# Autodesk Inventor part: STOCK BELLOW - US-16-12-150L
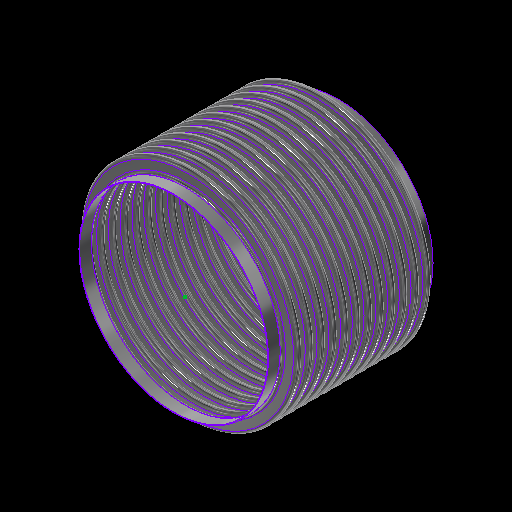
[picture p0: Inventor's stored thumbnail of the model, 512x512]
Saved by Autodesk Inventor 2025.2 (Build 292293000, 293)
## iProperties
Category: 16 GA (0.060 THICK)
RuleStatus: InUse
Created: 2024-01
Part Number: STOCK BELLOW - US-16-12-150L
Project: =STOCK BELLOWS: <Stock Number><SFILL>
Material: ASTM A240-304
Description: =STOCK BELLOWS: <Stock Number>, <SID_> I.D., <SOD_> O.D., <SPLY_> PLY, <Category>, <SNET_CONS> CONS.<PITCH_><STANGENT_> TANGENT<SFILL>
Document SubType Name: Sheet Metal
Designer: GS
Stock Number: U.S-16-12-150L
Surface Area: 26179.6 cm^2
Volume: 1985.95 cm^3
Sheet Metal Rule: Default
Appearance: STAINLESS STEEL
Mass: 16001.4 g
Density: 8.05729 g/cm^3
THK: 0.036
ID: 3.500
OD: 4.250
CONS_: 2
PITCH: 0.500
TANGENT: 0.500
BELLOWS_UPSET: 0.000
d79: 1.000
d82: 1.000
d83: 26.000
d84: 24.000
d174: 8
d214: 8
STHK_: 0.060
SID_: 16.000
SOD_: 18.500
SPITCH_: 1.000
STANGENT__: 1.000
SBELLOWS_UPSET_: 0.000
SDIFF_TAN: 1.000
d252: 2
d275: 2
d287: 0.050
d289: 0.500
d290: 0.000
SOD_NECK: 16 1/8
PLY: 1
PSET: 4.178
PBAR: 1.035
COUNTER: 1.500
NET_TUBE: 3.071
CONS: 2
S_CONS: 0
NET_CONS: 2
ID_M: 88.90 mm
OD_M: 107.95 mm
THK_M: 0.91 mm
ID_U: 3.500 in
OD_U: 4.250 in
THK_U: 0.036 in
TANGENT2: 0.500
TAN_TO_TAN: 1.000 in
d80: 2.571
d81: 10
SID: 2.375
SCONS_: 12
SPITCH: 0.250
STANGENT_: 1.000
SBELLOWS_UPSET: 0.000
SNET_CONS: 12
SS_CONS: 0
SCONS: 8
d190: 8
d191: 1
d192: 1
d193: 8
d194: 0
SIZE: 16.00
PRESSURE: 150
d230: 8
STANGENT: 4.000
SPLY_: 1
d233: 8
d234: 0
d263: 2
d265: 1
d268: 2
d269: 0
d286: 2
d288: 1
d291: 2
d292: 0
SREROLL: 0.750
BLETP: 1.000 ul
PRES_Copy: 85
MATTABLE: 20 GA (0.036 THICK)
PART_NUMBER: U.S-16-12-150L
PITCH_: =, <SPITCH_> PITCH,
CFILL: .
SFILL: .
MESH: ,
COMP: 2.28
EXT: 1.14
LAT: 0.52
ANG: 573
ASR: 2982
LSR: 8318
ANSR: 1742
PRES: 150
COMPM: 22.8
EXTM: 11.4
LATM: 5.20
ASRM: 522.238
PRESM: 10.342
LSRM: 1456.731
ANSRM: 305.076
TEMPMIN: 20
TEMPMAX: 800
TEMPMINM: -7
TEMPMAXM: 427
WEIGHTM: 16.001
WEIGHT: 35.277
Author: GS
Keywords: 20 GA (0.036 THICK)
Comments: =STOCK BELLOW - <STOCK NUMBER>
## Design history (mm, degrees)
sketch "Sketch2"
  geometry: L1 (0, -177.245)-(0, 562.856) reference; L2 (45.364, 0)-(44.45, 0); L3 (48.082, -2.718)-(50.343, -2.718); L4 (48.082, -3.632)-(50.343, -3.632); L5 (50.343, -9.982)-(48.082, -9.982); L6 (50.343, -9.068)-(48.082, -9.068); L7 (45.364, -12.7)-(44.45, -12.7); L8 (48.082, 0)-(48.082, -12.7); L9 (50.343, -6.35)-(53.975, -6.35); L10 (44.45, 0)-(44.45, -12.7); L11 (20.376, 102.841)-(20.376, 101.926); L12 (58.262, 457.127)-(58.262, 349.177); L13 (58.262, 444.427)-(58.262, 336.477); L14 (93.133, -58.817)-(93.133, -71.517); L15 (118.746, -66.401)-(118.746, -66.401); L16 (50.343, -9.068)-(50.343, -9.982); L17 (48.082, -9.068)-(48.082, -9.982); L18 (48.082, -9.525)-(50.343, -9.525); L19 (53.975, 0)-(53.975, -12.7); L20 (-50.343, -9.068)-(-50.343, -9.982); L21 (-50.343, -2.718)-(-48.082, -2.718); L22 (-50.343, -3.632)-(-48.082, -3.632); L23 (-48.082, -9.068)-(-50.343, -9.068); L24 (-50.343, -9.525)-(-48.082, -9.525); L25 (-48.082, -9.982)-(-50.343, -9.982); L26 (-48.082, -9.068)-(-48.082, -9.982); L27 (-44.45, 0.653)-(-44.45, -12.047); L28 (-48.082, -6.35)-(-44.45, -6.35); L29 (-50.343, 0.653)-(-50.343, -12.7); L30 (-53.061, 0)-(-53.975, 0); L31 (-53.975, 0)-(-53.975, -12.7); L32 (-53.061, -12.7)-(-53.975, -12.7); A1 r 2.718 centre (48.082, 0) between (45.364, 0) and (48.082, -2.718); A2 r 3.632 centre (48.082, 0) between (44.45, 0) and (48.082, -3.632); A3 r 3.632 centre (50.343, -6.35) between (50.343, -9.982) and (50.343, -2.718); A4 r 2.718 centre (50.343, -6.35) between (50.343, -9.068) and (50.343, -3.632); A5 r 2.718 centre (48.082, -12.7) between (48.082, -9.982) and (45.364, -12.7); A6 r 3.632 centre (48.082, -12.7) between (48.082, -9.068) and (44.45, -12.7); A7 r 3.175 centre (50.343, -6.35) between (50.343, -9.525) and (53.518, -6.35); A8 r 3.175 centre (48.082, -12.7) between (48.082, -9.525) and (44.907, -12.7); A9 r 2.718 centre (-50.343, -12.7) between (-50.343, -9.982) and (-53.061, -12.7); A10 r 2.718 centre (-48.082, -6.35) between (-48.082, -9.068) and (-48.082, -3.632); A11 r 3.175 centre (-48.082, -6.35) between (-48.082, -9.525) and (-44.907, -6.35); A12 r 3.632 centre (-48.082, -6.35) between (-48.082, -9.982) and (-48.082, -2.718); A13 r 3.175 centre (-50.343, -12.7) between (-50.343, -9.525) and (-53.518, -12.7); A14 r 3.632 centre (-50.343, -12.7) between (-50.343, -9.068) and (-53.975, -12.7); A15 r 2.718 centre (-50.343, 0) between (-53.061, 0) and (-50.343, -2.718); A16 r 3.632 centre (-50.343, 0) between (-53.975, 0) and (-50.343, -3.632); 10 further points
  constraints: 62 end point, 38 point on circle, 20 tangent, 16 centre point, 12 parallel, 9 midpoint, 7 vertical, 6 coincident, 6 concentric, 6 point on line, 4 equal radius, 4 perpendicular, 3 horizontal, 1 collinear, 1 horizontal alignment, 10 other
  dimensions: "THK" = 0.9144 distance of L11.start L11.end; "ID" = 88.9 distance of L11.end point (20.376, 13.026); "OD" = 107.95 distance of L12.start L12.end; "PITCH" = 12.7 distance of L12.start L13.start; "TANGENT" = 12.7 distance of L14.start L14.end; "BELLOWS_UPSET" = 0 distance of L15.start L15.end; "d43" = 88.9 diameter of L10 L1 (= ID); "d44" = 107.95 diameter of L9.end L1 (= OD); "d45" = 0.9144 distance between parallel lines of L5 L6 (computed from THK, PLY); "d46" = 3.6322 radius of A3 (computed from PITCH, THK, PLY); "UPSET_PITCH" = 12.7 distance of L2.end L7.end (derived); "SIDEWALL_ANGLE" = 360 deg dimension on L3 L9 (derived); "CON_GAP" = 5.4356 distance of point (48.082, -9.068) point (48.082, -3.632) (derived); "TAN1" = 4.98728 dimension on A8 (derived); "TAN2" = 4.98728 dimension on A7 (derived); "LEG1" = 2.2606 distance of L18.start L18.end (derived); "d278" = 0.9144 distance between parallel lines of L25 L23 (derived); "d279" = 3.6322 radius of A12 (derived); "d280" = 12.7 distance of L30.end L31.end (derived); "d281" = 360 deg dimension on L21 L28 (derived); "d282" = 5.4356 distance of point (-50.343, -9.068) point (-50.343, -3.632) (derived); "d283" = 4.98728 dimension on A13 (derived); "d284" = 4.98728 dimension on A11 (derived); "d285" = 2.2606 distance of L24.start L24.end (derived); "d293" = 88.9 diameter of L27 L1 (derived); "d294" = 107.95 diameter of L31 L1 (derived)
  node "Sketch Rectangular Pattern1" dims "d31" = 25.4, "ID" = 88.9
  node "Sketch Rectangular Pattern2" dims "d39" = 25.4, "PITCH" = 12.7
revolve "CONS" stored, may be unused: angle "d48" = 90 deg
node "BELLOW MIDPLANE"
pattern_linear "Rectangular Pattern2" dims "d52" = 12.7 (= UPSET_PITCH)
sketch "Sketch5"
  geometry: C1 r 45.364 at (0, 0) reference; C2 r 44.45 at (0, 0) reference
extrude "TANGENT" new body sketch "Sketch5" distance "d53" = 12.7 (= TANGENT); taper "d54" = 0 deg
revolve "SAMETAN" stored, may be unused: angle "d65" = 90 deg
revolve "DIFFTAN" stored, may be unused: angle "d70" = 90 deg
sketch "Sketch9"
  geometry: L1 (53.319, 0)-(-53.319, 0) reference; L2 (0, -17.78)-(0, 17.78) reference; L3 (38.085, 0)-(-38.085, 0); L4 (38.085, -11.906)-(38.085, 11.906); L5 (25.385, -11.906)-(25.385, 11.906); L6 (13.15, 11.906)-(13.15, -11.906); L7 (-25.385, -11.906)-(-25.385, 11.906); L8 (-38.085, -11.906)-(-38.085, 11.906); L9 (37.291, -11.906)-(37.291, 11.906); L10 (38.085, -11.906)-(37.291, -11.906); L11 (38.085, 11.906)-(37.291, 11.906); L12 (13.546, 11.906)-(12.753, 11.906); L13 (12.753, 11.906)-(12.753, -11.906); L14 (12.753, -11.906)-(13.546, -11.906); L15 (13.546, -11.906)-(13.546, 11.906); L16 (-13.546, 11.906)-(-13.546, -11.906); L17 (-13.15, 11.906)-(-13.15, -11.906); L18 (-13.546, -11.906)-(-12.753, -11.906); L19 (-12.753, -11.906)-(-12.753, 11.906); L20 (-12.753, 11.906)-(-13.546, 11.906); L21 (-38.085, -11.906)-(-37.291, -11.906); L22 (-37.291, -11.906)-(-37.291, 11.906); L23 (-37.291, 11.906)-(-38.085, 11.906); L24 (-38.085, 11.906)-(-38.085, -11.906); L25 (38.085, -0.397)-(-38.085, -0.397); L26 (-38.085, -0.397)-(-38.085, 0.397); L27 (-38.085, 0.397)-(38.085, 0.397); L28 (38.085, 0.397)-(38.085, -0.397); L29 (-38.085, 11.906)-(38.085, 11.906); L30 (38.085, 11.906)-(38.085, 12.7); L31 (38.085, 12.7)-(-38.085, 12.7); L32 (-38.085, 12.7)-(-38.085, 11.906); L33 (38.085, -11.906)-(-38.085, -11.906); L34 (-38.085, -11.906)-(-38.085, -12.7); L35 (-38.085, -12.7)-(38.085, -12.7); L36 (38.085, -12.7)-(38.085, -11.906); 30 further points
  constraints: 68 end point, 13 midpoint, 13 parallel, 8 horizontal, 7 perpendicular, 6 equal length, 3 point on line, 2 vertical, 14 other
  dimensions: "d115" = 23.8125 distance of L4.start L4.end (derived); "d116" = 12.7 distance between parallel lines of L4 L5 (derived); "d117" = 12.23516 distance between parallel lines of L5 L6 (derived); "d125" = 38.53427 distance between parallel lines of L7 L6 (derived); "d127" = 12.7 distance between parallel lines of L8 L7 (derived); "d128" = 24.93516 distance between parallel lines of L6 L4 (derived); "d130" = 76.16943 distance between parallel lines of L8 L4 (derived); "RULER_THK" = 0.79375 distance between parallel lines of L4 L9; "d135" = 0.79375 distance of L13.end L14.end (derived); "d138" = 26.29911 distance of L13.end L16.end (derived); "d143" = 0.79375 distance of L22.end L8.end (derived); "d144" = 0.79375 distance between parallel lines of L27 L25 (derived)
extrude "RULER" join sketch "Sketch9" distance "d149" = 0.79375 (derived); taper "d150" = 0 deg
extrude "BARS" join sketch "Sketch9" distance "d151" = 0.79375 (derived); taper "d152" = 0 deg
pattern_linear "Rectangular Pattern4" dims "d155" = 26.29911 (derived)
sketch "Sketch13"
  geometry: L1 (93.149, -52.467)-(93.149, -77.867); L2 (204.724, 0)-(203.2, 0); L3 (204.724, -25.4)-(203.2, -25.4); L4 (227.838, -19.812)-(210.312, -19.812); L5 (227.838, -18.288)-(210.312, -18.288); L6 (227.838, -12.7)-(234.95, -12.7); L7 (210.312, -5.588)-(227.838, -5.588); L8 (210.312, 0)-(210.312, -25.4); L9 (203.2, 0)-(203.2, -25.4); L10 (58.254, -26.531)-(58.254, -496.431); L11 (58.254, -51.931)-(58.254, -521.831); L12 (58.254, -102.731)-(58.254, -572.631); L13 (58.254, -128.131)-(58.254, -598.031); L14 (58.254, -153.531)-(58.254, -623.431); L15 (58.254, -178.931)-(58.254, -648.831); L16 (58.254, -204.331)-(58.254, -674.231); L17 (58.254, -77.331)-(58.254, -547.231); L18 (20.376, 103.45)-(20.376, 101.926); L19 (210.312, -7.112)-(227.838, -7.112); L20 (0, -829.767)-(0, 258.986) reference; L21 (-46.99, 0)-(281.94, 0) reference; A1 r 5.588 centre (210.312, 0) between (204.724, 0) and (210.312, -5.588); A2 r 5.588 centre (210.312, -25.4) between (210.312, -19.812) and (204.724, -25.4); A3 r 7.112 centre (210.312, -25.4) between (210.312, -18.288) and (203.2, -25.4); A4 r 5.588 centre (227.838, -12.7) between (227.838, -18.288) and (227.838, -7.112); A5 r 7.112 centre (227.838, -12.7) between (227.838, -19.812) and (227.838, -5.588); A6 r 7.112 centre (210.312, 0) between (203.2, 0) and (210.312, -7.112); 6 further points; 1 other entity
  constraints: 38 end point, 15 point on circle, 9 tangent, 6 centre point, 6 parallel, 5 vertical alignment, 4 point on line, 4 vertical, 3 coincident, 3 concentric, 2 collinear, 2 equal radius, 1 horizontal, 1 perpendicular, 23 other
  dimensions: "SBELLOWS_UPSET_" = 0 distance of point (118.762, -66.401) point (118.762, -66.401); "STOTAL_THK_BELLOW__" = 1.524 distance between parallel lines of L4 L5 (derived); "d224" = 7.112 radius of A5 (derived); "d225" = 25.4 distance of L2.end L3.end (derived); "SSIDEWALL_ANGLE_" = 360 deg dimension on L7 L6 (derived); "SSCON_GAP_" = 11.176 distance of point (210.312, -18.288) point (210.312, -7.112) (derived); "d235" = 406.4 diameter of L9 L20 (derived); "d236" = 469.9 diameter of L6.end L20 (derived)
  node "Sketch Rectangular Pattern4" dims "d228" = 25.4
  node "Sketch Rectangular Pattern5" dims "d229" = 25.4
revolve "SBELLOW" stored, may be unused: angle "d197" = 90 deg
pattern_linear "Rectangular Pattern5" dims "d204" = 25.4 (derived)
revolve "STANGENT" stored, may be unused: angle "d240" = 90 deg
revolve "SSAMETAN" stored, may be unused: angle "d241" = 90 deg
revolve "SDIFFTAN" stored, may be unused: angle "d246" = 90 deg
revolve "INVCON" stored, may be unused: angle "d295" = 90 deg
pattern_linear "Rectangular Pattern6" dims "d298" = 12.7 (derived)
revolve "INVTANGENT" stored, may be unused: angle "d302" = 90 deg
revolve "INVSAMETAN" stored, may be unused: angle "d307" = 90 deg
revolve "INVDIFFTAN" stored, may be unused: angle "d312" = 90 deg
sketch "ID BELLOW MOUNT CALC"
  geometry: L1 (44.45, 0)-(38.1, 0); L2 (38.1, 0)-(38.1, 12.7); L3 (38.1, 12.7)-(44.45, 12.7); L4 (44.45, 12.7)-(44.45, 0); L5 (36.513, 12.7)-(35.598, 12.7); L6 (35.598, 12.7)-(35.598, 0); L7 (35.598, 0)-(36.513, 0); L8 (36.513, 0)-(36.513, 12.7); L9 (0, -2.54)-(0, 15.24) reference; L10 (-8.89, 0)-(53.34, 0) reference; 1 further point
  constraints: 16 end point, 5 parallel, 2 collinear, 2 horizontal, 2 perpendicular
  dimensions: "d314" = 12.7 distance of L5.end L6.end (derived); "d315" = 0.9144 distance of L5.start L5.end (derived); "IG" = 1.5875 distance between parallel lines of L2 L8; "PIPE_OD" = 88.9 diameter of L4 L9; "PIPE_WALL" = 6.35 distance of L2.end L3.end; "ID_MT_BELLOW" = 71.1962 diameter of L6 L9 (derived)
revolve "CFILL" stored, may be unused: angle "d320" = 90 deg
pattern_linear "Rectangular Pattern7" dims "d323" = 12.7 (derived)
revolve "SFILL" stored, may be unused: angle "d324" = 90 deg
pattern_linear "Rectangular Pattern8" dims "d327" = 25.4 (derived)
node "STOCK BELLOW MIDPLANE"
node "BELLOW"
sketch "Sketch6"
  geometry: L1 (-12.7, 45.364)-(0, 45.364); L2 (0, 45.364)-(0, 44.45); L3 (0, 44.45)-(-12.7, 44.45); L4 (-12.7, 44.45)-(-12.7, 45.364); L5 (10.16, 0)-(-60.96, 0) reference; L6 (-38.1, -89.422)-(-38.1, 153.44) reference; 1 further point
  constraints: 8 end point, 2 parallel, 1 horizontal, 1 perpendicular
  dimensions: "d61" = 12.7 distance of L2.end L3.end (derived); "d62" = 0.9144 distance of L1.end L2.end (derived); "d63" = 88.9 diameter of L3 L5 (derived); "d64" = 25.4 distance between parallel lines of L4 L6 (derived)
sketch "Sketch12"
  geometry: 1 further point
sketch "Sketch14"
  geometry: L1 (-25.4, 204.724)-(0, 204.724); L2 (0, 204.724)-(0, 203.2); L3 (0, 203.2)-(-25.4, 203.2); L4 (-25.4, 203.2)-(-25.4, 204.724); L5 (5.08, 0)-(-30.48, 0) reference; L6 (0, -40.945)-(0, 245.669) reference; 1 further point
  constraints: 8 end point, 2 parallel, 1 collinear, 1 horizontal, 1 perpendicular
  dimensions: "d237" = 1.524 distance of L3.end L1.start (derived); "d238" = 406.4 diameter of L3 L5 (derived); "d239" = 25.4 distance of L1.start L1.end (derived); "SOD_NECK" = 409.448 diameter of L1 L5 (derived)
sketch "Sketch15"
  geometry: L1 (-40.945, 0)-(245.669, 0) reference; L2 (203.2, -304.8)-(204.724, -304.8); L3 (204.724, -304.8)-(204.724, -330.2); L4 (204.724, -330.2)-(203.2, -330.2); L5 (203.2, -330.2)-(203.2, -304.8); L6 (0, -398.78)-(0, 81.28) reference; 1 further point
  constraints: 8 end point, 2 parallel, 1 horizontal, 1 perpendicular
  dimensions: "d205" = 25.4 distance of L4.end L2.start (derived); "d206" = 1.524 distance of L3.end L4.end (derived); "d207" = 406.4 diameter of L5 L6 (derived); "d208" = 304.8 distance between parallel lines of L1 L2 (derived)
node "TANGENT_"
node "SAME_TAN"
sketch "Sketch8"
  geometry: L1 (45.364, -25.4)-(44.45, -25.4); L2 (44.45, -25.4)-(44.45, -38.1); L3 (44.45, -38.1)-(45.364, -38.1); L4 (45.364, -38.1)-(45.364, -25.4); L5 (0, -48.26)-(0, 22.86) reference; L6 (-89.422, 0)-(153.44, 0) reference; 1 further point
  constraints: 8 end point, 2 parallel, 1 horizontal, 1 perpendicular
  dimensions: "d66" = 88.9 diameter of L2 L5 (derived); "TOTAL_THK_BELLOW" = 0.9144 distance of L2.end L3.end (derived); "d68" = 25.4 distance between parallel lines of L1 L6 (derived); "d69" = 12.7 distance of L1.end L2.end (derived)
node "DIFF_TAN"
node "Sketch Rectangular Pattern3" dims "d138" = 26.29911 (derived), "d141" = 25.4
node "SBELLOW_"
node "STANGENT_"
node "SSAME_TAN"
sketch "Sketch16"
  geometry: L1 (204.724, -304.8)-(203.2, -304.8); L2 (203.2, -304.8)-(203.2, -330.2); L3 (203.2, -330.2)-(204.724, -330.2); L4 (204.724, -330.2)-(204.724, -304.8); L5 (0, -398.78)-(0, 81.28) reference; L6 (-40.945, 0)-(245.669, 0) reference; 1 further point
  constraints: 8 end point, 2 parallel, 1 horizontal, 1 perpendicular
  dimensions: "SDIFF_TAN" = 25.4 distance of L3.end L1.start; "d243" = 1.524 distance of L2.end L3.end (derived); "d244" = 304.8 distance between parallel lines of L1 L6 (derived); "d245" = 406.4 diameter of L2 L5 (derived)
node "SDIFF_TAN"
body "Solid15"
sketch "Sketch17"
  geometry: L1 (53.975, 12.7)-(53.061, 12.7); L2 (53.061, 12.7)-(53.061, 0); L3 (53.061, 0)-(53.975, 0); L4 (53.975, 0)-(53.975, 12.7); L5 (0, -2.54)-(0, 15.24) reference; L6 (-10.795, 0)-(64.77, 0) reference; 2 further points
  constraints: 8 end point, 2 parallel, 1 horizontal, 1 midpoint, 1 perpendicular, 1 point on line
  dimensions: "INVTANGENT" = 12.7 distance of L3.end L1.start (derived); "d300" = 0.9144 distance of L1.start L1.end (derived); "d301" = 107.95 diameter of L4 L5 (derived)
body "Solid16"
sketch "Sketch18"
  geometry: L1 (53.975, -25.4)-(53.061, -25.4); L2 (53.061, -25.4)-(53.061, -38.1); L3 (53.061, -38.1)-(53.975, -38.1); L4 (53.975, -38.1)-(53.975, -25.4); L5 (-10.795, 0)-(64.77, 0) reference; L6 (0, -48.26)-(0, 22.86) reference; 1 further point
  constraints: 8 end point, 2 parallel, 1 horizontal, 1 perpendicular
  dimensions: "d303" = 25.4 distance between parallel lines of L1 L5 (derived); "d304" = 12.7 distance of L3.end L1.start (derived); "d305" = 0.9144 distance of L2.end L3.end (derived); "d306" = 107.95 diameter of L4 L6 (derived)
body "Solid17"
sketch "Sketch19"
  geometry: L1 (53.975, -25.4)-(53.061, -25.4); L2 (53.061, -25.4)-(53.061, -38.1); L3 (53.061, -38.1)-(53.975, -38.1); L4 (53.975, -38.1)-(53.975, -25.4); L5 (0, -48.26)-(0, 22.86) reference; L6 (-10.795, 0)-(64.77, 0) reference; 1 further point
  constraints: 8 end point, 2 parallel, 1 horizontal, 1 perpendicular
  dimensions: "d308" = 12.7 distance of L1.end L2.end (derived); "d309" = 107.95 diameter of L4 L5 (derived); "d310" = 0.9144 distance of L2.end L3.end (derived); "d311" = 25.4 distance between parallel lines of L1 L6 (derived)
body "Solid18"
body "Solid19"
body "Solid20"
other parameters: "BMPL" = -152.4, "PSET" = 106.1212 (computed from OD, THK, PLY) [user parameter], "PBAR" = 26.29911 (= 0.570796 x PITCH + OD - ID) [user parameter; used in 1 equation term], "COUNTER" = 15 [user parameter], "NET_TUBE" = 77.99823 (computed from CONS_, PBAR, TANGENT) [user parameter], "S_CONS" = 0 [user parameter; used in 1 equation term], "ID_M" = 88.9 (= ID) [user parameter], "OD_M" = 107.95 (= OD) [user parameter], "THK_M" = 0.9144 (= THK) [user parameter], "ID_U" = 88.9 (= ID) [user parameter], "OD_U" = 107.95 (= OD) [user parameter], "THK_U" = 0.9144 (= THK) [user parameter], "D_UNITS" = 0 [user parameter], "TANGENT2" = 12.7 [user parameter], "TAN_TO_TAN" = 25.4 [user parameter], "OD_NECK" = 90.7288 [user parameter], "d79" = 25.4, "d80" = 65.29823 [user parameter], "d82" = 25.4, "d83" = 660.4, "d84" = 609.6, "sa_0" = 4, "FRAME_THK" = 0.79375 [user parameter], "CON_FLAT" = 12.23516 [user parameter], "SID" = 60.325 [user parameter], "SPITCH" = 6.35 [user parameter], "STANGENT_" = 25.4 [user parameter], "SBELLOWS_UPSET" = 0 [user parameter], "SS_CONS" = 0 [user parameter], "STAN_TO_TAN_" = 304.8 [user parameter], "d100" = 1.524 [user parameter], "d191" = 25.4 [user parameter], "d194" = 0 [user parameter], "STANGENT" = 101.6 [user parameter], "d234" = 0 [user parameter], "SUPSET_PITCH_" = 25.4 [user parameter], "d269" = 0 [user parameter], "d287" = 1.27, "d289" = 12.7, "d290" = 0, "d292" = 0 [user parameter], "Thickness" = 3.048 (derived), "KFactor" = 4.4, "BendRadius" = 3.048 (derived), "BendReliefWidth" = 3.048 (derived), "BendReliefDepth" = 1.524 (derived), "CornerReliefSize" = 12.192 (derived), "SeamGap" = 0.00508, "MinimumRemnant" = 6.096 (derived), "TransitionRadius" = 3.048 (derived), "JacobiRadiusSize" = 3.048 (derived), "GapSize" = 3.048 (derived), "SREROLL" = 19.05 [user parameter], "CUR_STK_PITCH" = 25.4 [user parameter], "d328" = -152.4 (derived), "ASR" = 29820 [user parameter], "LSR" = 83180 [user parameter], "ANSR" = 17420 [user parameter], "BLETP" = 1 [user parameter], "ASRM" = 5222.3766 [user parameter], "PRESM" = 103.41975 [user parameter], "LSRM" = 14567.3134 [user parameter], "ANSRM" = 3050.7646 [user parameter], "TEMPMIN" = 2664.83333 [user parameter], "TEMPMAX" = 6998.16667 [user parameter], "TEMPMINM" = 2664.83333 [user parameter], "TEMPMAXM" = 6998.16667 [user parameter], "WEIGHT" = 160.01403 [user parameter], "WEIGHTM" = 0.16001 [user parameter]
